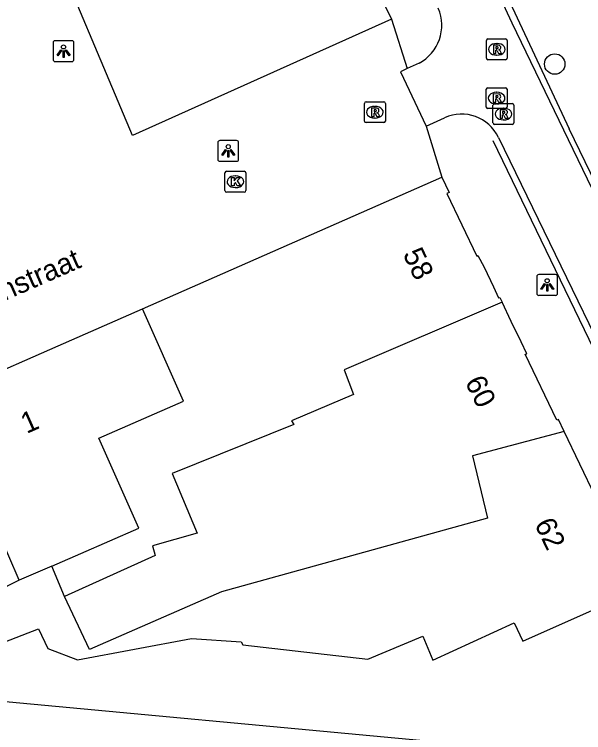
# Model space of a CAD drawing. Extents: x 161087 to 161922, y 382574 to 383873.
# Drawn here: x 161637.33 to 161664.66, y 382920.38 to 382954.87 of the extents above; entities that cross this region are included whole.
import ezdxf

# ---------------------------------------------------------------- set-up
doc = ezdxf.new("R2010")
doc.units = 0
for name, color, linetype in [('IMGEO_Boom', 7, 'Continuous'), ('IMGEO_Kolk', 7, 'Continuous'), ('IMGEO_Lichtpunt', 7, 'Continuous'), ('IMGEO_Lijnafwatering', 7, 'Continuous'), ('IMGEO_Openbare_ruimte_label', 7, 'Continuous'), ('IMGEO_Pand', 7, 'Continuous'), ('IMGEO_Pand_nummerreeks', 7, 'Continuous'), ('IMGEO_Rioolput', 7, 'Continuous'), ('IMGEO_Voetgangersgebied_gesloten', 7, 'Continuous'), ('IMGEO_Voetpad_open', 7, 'Continuous')]:
    doc.layers.add(name, color=color, linetype=linetype)

msp = doc.modelspace()

# ---------------------------------------------------------------- linework, layer by layer
at = {"layer": 'IMGEO_Boom'}
msp.add_circle((161663.274, 382952.485), 0.489, dxfattribs=at)
at = {"layer": 'IMGEO_Kolk'}
for p, q in [((161647.443, 382946.408), (161647.443, 382947.26)), ((161647.518, 382947.334), (161648.37, 382947.334)), ((161648.444, 382947.26), (161648.444, 382946.408)), ((161647.931, 382947.114), (161647.956, 382947.114)), ((161647.954, 382946.554), (161647.929, 382946.554)), ((161648.37, 382946.334), (161647.518, 382946.334))]:
    msp.add_line(p, q, dxfattribs=at)
for points in [[(161647.443, 382946.408), (161647.443, 382947.26)], [(161647.518, 382947.334), (161648.37, 382947.334)], [(161648.444, 382947.26), (161648.444, 382946.408)], [(161647.764, 382947.034), (161647.887, 382947.034), (161647.887, 382946.883), (161648.017, 382947.034), (161648.181, 382947.034), (161648.035, 382946.883), (161648.188, 382946.634), (161648.036, 382946.634), (161647.951, 382946.798), (161647.887, 382946.731), (161647.887, 382946.634), (161647.764, 382946.634), (161647.764, 382947.034)], [(161648.37, 382946.334), (161647.518, 382946.334)]]:
    msp.add_lwpolyline(points, dxfattribs=at)
for centre, start, end in [((161647.52, 382947.258), 91.552, 178.448), ((161647.52, 382947.258), 91.552, 178.448), ((161648.368, 382947.258), 1.552, 88.448), ((161648.368, 382947.258), 1.552, 88.448), ((161647.52, 382946.41), 181.552, 268.448), ((161647.52, 382946.41), 181.552, 268.448), ((161648.368, 382946.41), 271.552, 358.448), ((161648.368, 382946.41), 271.552, 358.448)]:
    msp.add_arc(centre, 0.0765, start, end, dxfattribs=at)
for centre, major_axis, ratio, start_param, end_param in [((161647.93, 382946.834), (-0.387, 0.002), 0.722429, 4.712389, 7.853982), ((161647.955, 382946.834), (-0.39, 0.002), 0.717154, 1.570796, 4.712389)]:
    msp.add_ellipse(centre, major_axis=major_axis, ratio=ratio, start_param=start_param, end_param=end_param, dxfattribs=at)
at = {"layer": 'IMGEO_Lichtpunt'}
for p, q in [((161639.192, 382953.509), (161639.192, 382952.702)), ((161639.192, 382953.509), (161639.192, 382952.702)), ((161640.094, 382953.604), (161639.286, 382953.604)), ((161640.094, 382953.604), (161639.286, 382953.604)), ((161640.188, 382952.702), (161640.188, 382953.509)), ((161640.188, 382952.702), (161640.188, 382953.509)), ((161639.286, 382952.608), (161640.094, 382952.608)), ((161639.286, 382952.608), (161640.094, 382952.608)), ((161647.101, 382948.717), (161647.101, 382947.91)), ((161647.101, 382948.717), (161647.101, 382947.91)), ((161648.003, 382948.812), (161647.195, 382948.812)), ((161648.003, 382948.812), (161647.195, 382948.812)), ((161648.097, 382947.91), (161648.097, 382948.717)), ((161648.097, 382947.91), (161648.097, 382948.717)), ((161647.195, 382947.816), (161648.003, 382947.816)), ((161647.195, 382947.816), (161648.003, 382947.816)), ((161662.414, 382942.279), (161662.414, 382941.472)), ((161662.414, 382942.279), (161662.414, 382941.472)), ((161663.316, 382942.374), (161662.508, 382942.374)), ((161663.316, 382942.374), (161662.508, 382942.374)), ((161663.41, 382941.472), (161663.41, 382942.279)), ((161663.41, 382941.472), (161663.41, 382942.279)), ((161662.508, 382941.378), (161663.316, 382941.378)), ((161662.508, 382941.378), (161663.316, 382941.378))]:
    msp.add_line(p, q, dxfattribs=at)
for points in [[(161639.566, 382953.173), (161639.605, 382953.145), (161639.417, 382952.883), (161639.379, 382952.91), (161639.566, 382953.173)], [(161639.668, 382953.125), (161639.715, 382953.125), (161639.715, 382952.803), (161639.668, 382952.803), (161639.668, 382953.125)], [(161639.778, 382953.145), (161639.816, 382953.172), (161640.003, 382952.91), (161639.964, 382952.882), (161639.778, 382953.145)], [(161647.475, 382948.381), (161647.514, 382948.353), (161647.326, 382948.091), (161647.288, 382948.118), (161647.475, 382948.381)], [(161647.577, 382948.333), (161647.624, 382948.333), (161647.624, 382948.011), (161647.577, 382948.011), (161647.577, 382948.333)], [(161647.687, 382948.353), (161647.725, 382948.38), (161647.912, 382948.118), (161647.873, 382948.09), (161647.687, 382948.353)], [(161662.788, 382941.943), (161662.827, 382941.915), (161662.639, 382941.653), (161662.601, 382941.68), (161662.788, 382941.943)], [(161662.89, 382941.895), (161662.937, 382941.895), (161662.937, 382941.573), (161662.89, 382941.573), (161662.89, 382941.895)], [(161663, 382941.915), (161663.038, 382941.942), (161663.225, 382941.68), (161663.186, 382941.652), (161663, 382941.915)]]:
    msp.add_lwpolyline(points, dxfattribs=at)
for centre in [(161639.691, 382953.307), (161647.6, 382948.515), (161662.913, 382942.077)]:
    msp.add_circle(centre, 0.0994, dxfattribs=at)
for centre, start, end in [((161639.286, 382953.509), 90, 180), ((161639.286, 382953.509), 90, 180), ((161640.094, 382953.509), 0, 90), ((161640.094, 382953.509), 0, 90), ((161639.286, 382952.702), 180, 270), ((161639.286, 382952.702), 180, 270), ((161640.094, 382952.702), 270, 0), ((161640.094, 382952.702), 270, 360), ((161647.195, 382948.717), 90, 180), ((161647.195, 382948.717), 90, 180), ((161648.003, 382948.717), 0, 90), ((161648.003, 382948.717), 0, 90), ((161647.195, 382947.91), 180, 270), ((161647.195, 382947.91), 180, 270), ((161648.003, 382947.91), 270, 0), ((161648.003, 382947.91), 270, 360), ((161662.508, 382942.279), 90, 180), ((161662.508, 382942.279), 90, 180), ((161663.316, 382942.279), 0, 90), ((161663.316, 382942.279), 0, 90), ((161662.508, 382941.472), 180, 270), ((161662.508, 382941.472), 180, 270), ((161663.316, 382941.472), 270, 0), ((161663.316, 382941.472), 270, 360)]:
    msp.add_arc(centre, 0.0946, start, end, dxfattribs=at)
at = {"layer": 'IMGEO_Lijnafwatering'}
for points in [[(161646.729, 382986.194), (161663.964, 382949.371)], [(161675.74, 382925.074), (161663.964, 382949.371)], [(161660.31, 382948.808), (161672.527, 382923.509)]]:
    msp.add_lwpolyline(points, dxfattribs=at)
at = {"layer": 'IMGEO_Pand'}
for points in [[(161655.439, 382954.633), (161643.006, 382949.054), (161638.697, 382959.289), (161626.193, 382950.825), (161625.343, 382952.069)], [(161655.054, 382955.426), (161655.439, 382954.633)], [(161643.484, 382940.731), (161657.862, 382947.045)], [(161657.862, 382947.045), (161658.208, 382946.323), (161658.091, 382946.266), (161659.532, 382943.261), (161659.589, 382943.296), (161659.885, 382942.731), (161660.336, 382941.783), (161660.577, 382941.261), (161660.636, 382941.271), (161660.745, 382941.043)], [(161660.745, 382941.043), (161653.163, 382937.804), (161653.617, 382936.609), (161650.638, 382935.344), (161650.748, 382935.18), (161644.908, 382932.825), (161646.11, 382929.955), (161643.965, 382929.344), (161644.094, 382928.879), (161639.738, 382926.918)], [(161663.732, 382934.836), (161663.457, 382935.408), (161663.379, 382935.386), (161661.86, 382938.545), (161661.938, 382938.563), (161661.662, 382939.138), (161661.183, 382940.128), (161660.745, 382941.043)], [(161634.051, 382936.588), (161635.28, 382937.128), (161639.428, 382938.95), (161643.484, 382940.731)], [(161639.126, 382928.376), (161643.302, 382930.204), (161641.393, 382934.514), (161645.452, 382936.291), (161643.484, 382940.731)], [(161663.732, 382934.836), (161659.32, 382933.67), (161660.052, 382930.681), (161647.274, 382927.136), (161640.934, 382924.374), (161639.738, 382926.918)], [(161667.399, 382927.281), (161665.99, 382930.134), (161663.732, 382934.836)], [(161637.568, 382927.694), (161636.555, 382930.011)], [(161639.126, 382928.376), (161637.568, 382927.694)], [(161639.738, 382926.918), (161639.126, 382928.376)], [(161637.568, 382927.694), (161636.378, 382927.106)], [(161636.378, 382927.106), (161636.612, 382924.641), (161638.495, 382925.369), (161638.941, 382924.412), (161640.368, 382923.88), (161645.84, 382924.901), (161648.221, 382924.746), (161648.306, 382924.594), (161654.296, 382923.905), (161656.944, 382925.011), (161657.424, 382923.853), (161661.322, 382925.645), (161661.745, 382924.763), (161667.399, 382927.281)], [(161664.212, 382919.123), (161658.688, 382919.827), (161633.982, 382922.123), (161627.845, 382919.44), (161626.374, 382922.805)]]:
    msp.add_lwpolyline(points, dxfattribs=at)
at = {"layer": 'IMGEO_Rioolput'}
for p, q in [((161659.991, 382952.765), (161659.991, 382953.617)), ((161660.066, 382953.691), (161660.918, 382953.691)), ((161660.479, 382953.471), (161660.504, 382953.471)), ((161660.992, 382953.617), (161660.992, 382952.765)), ((161660.502, 382952.911), (161660.477, 382952.911)), ((161660.918, 382952.691), (161660.066, 382952.691)), ((161660.06, 382951.347), (161660.912, 382951.347)), ((161659.985, 382950.421), (161659.985, 382951.273)), ((161660.473, 382951.127), (161660.498, 382951.127)), ((161660.986, 382951.273), (161660.986, 382950.421)), ((161654.216, 382950.671), (161655.068, 382950.671)), ((161654.141, 382949.745), (161654.141, 382950.597)), ((161654.629, 382950.451), (161654.654, 382950.451)), ((161655.142, 382950.597), (161655.142, 382949.745)), ((161660.912, 382950.347), (161660.06, 382950.347)), ((161660.311, 382949.658), (161660.311, 382950.51)), ((161660.386, 382950.584), (161661.238, 382950.584)), ((161660.496, 382950.567), (161660.471, 382950.567)), ((161660.799, 382950.364), (161660.824, 382950.364)), ((161661.312, 382950.51), (161661.312, 382949.658)), ((161655.068, 382949.671), (161654.216, 382949.671)), ((161654.652, 382949.891), (161654.627, 382949.891)), ((161660.822, 382949.804), (161660.797, 382949.804)), ((161661.238, 382949.584), (161660.386, 382949.584))]:
    msp.add_line(p, q, dxfattribs=at)
for points in [[(161659.991, 382952.765), (161659.991, 382953.617)], [(161660.066, 382953.691), (161660.918, 382953.691)], [(161660.992, 382953.617), (161660.992, 382952.765)], [(161660.58, 382953.389), (161660.328, 382953.391), (161660.328, 382952.991)], [(161660.328, 382952.991), (161660.452, 382952.991), (161660.452, 382953.153), (161660.463, 382953.153)], [(161660.506, 382953.31), (161660.452, 382953.31), (161660.452, 382953.229)], [(161660.452, 382953.229), (161660.504, 382953.229)], [(161660.51, 382953.124), (161660.581, 382952.991), (161660.721, 382952.991), (161660.656, 382953.117)], [(161660.918, 382952.691), (161660.066, 382952.691)], [(161660.06, 382951.347), (161660.912, 382951.347)], [(161659.985, 382950.421), (161659.985, 382951.273)], [(161660.574, 382951.045), (161660.322, 382951.047), (161660.322, 382950.647)], [(161660.986, 382951.273), (161660.986, 382950.421)], [(161654.216, 382950.671), (161655.068, 382950.671)], [(161660.322, 382950.647), (161660.446, 382950.647), (161660.446, 382950.809), (161660.457, 382950.809)], [(161660.5, 382950.966), (161660.446, 382950.966), (161660.446, 382950.885)], [(161660.446, 382950.885), (161660.498, 382950.885)], [(161660.504, 382950.78), (161660.575, 382950.647), (161660.715, 382950.647), (161660.65, 382950.773)], [(161654.141, 382949.745), (161654.141, 382950.597)], [(161654.73, 382950.369), (161654.478, 382950.371), (161654.478, 382949.971)], [(161655.142, 382950.597), (161655.142, 382949.745)], [(161660.912, 382950.347), (161660.06, 382950.347)], [(161660.311, 382949.658), (161660.311, 382950.51)], [(161660.386, 382950.584), (161661.238, 382950.584)], [(161661.312, 382950.51), (161661.312, 382949.658)], [(161654.478, 382949.971), (161654.602, 382949.971), (161654.602, 382950.133), (161654.613, 382950.133)], [(161654.656, 382950.29), (161654.602, 382950.29), (161654.602, 382950.209)], [(161654.602, 382950.209), (161654.654, 382950.209)], [(161654.66, 382950.104), (161654.731, 382949.971), (161654.871, 382949.971), (161654.806, 382950.097)], [(161660.9, 382950.282), (161660.648, 382950.284), (161660.648, 382949.884)], [(161660.648, 382949.884), (161660.772, 382949.884), (161660.772, 382950.046), (161660.783, 382950.046)], [(161660.826, 382950.203), (161660.772, 382950.203), (161660.772, 382950.122)], [(161660.772, 382950.122), (161660.824, 382950.122)], [(161660.83, 382950.017), (161660.901, 382949.884), (161661.041, 382949.884), (161660.976, 382950.01)], [(161655.068, 382949.671), (161654.216, 382949.671)], [(161661.238, 382949.584), (161660.386, 382949.584)]]:
    msp.add_lwpolyline(points, dxfattribs=at)
for centre, radius, start, end in [((161660.068, 382953.615), 0.0765, 91.552, 178.448), ((161660.068, 382953.615), 0.0765, 91.552, 178.448), ((161660.916, 382953.615), 0.0765, 1.552, 88.448), ((161660.916, 382953.615), 0.0765, 1.552, 88.448), ((161660.462, 382953.1), 0.0533, 26.0293, 88.6989), ((161660.488, 382953.418), 0.19, 274.7715, 282.9687), ((161660.512, 382953.214), 0.0964, 77.0061, 93.1865), ((161660.526, 382953.271), 0.0378, 276.6634, 79.6772), ((161660.579, 382953.279), 0.109, 350.3612, 89.416), ((161660.577, 382953.279), 0.112, 277.5842, 350.9817), ((161660.561, 382953.064), 0.108, 29.5134, 73.7905), ((161660.068, 382952.767), 0.0765, 181.552, 268.448), ((161660.068, 382952.767), 0.0765, 181.552, 268.448), ((161660.916, 382952.767), 0.0765, 271.552, 358.448), ((161660.916, 382952.767), 0.0765, 271.552, 358.448), ((161660.062, 382951.271), 0.0765, 91.552, 178.448), ((161660.062, 382951.271), 0.0765, 91.552, 178.448), ((161660.91, 382951.271), 0.0765, 1.552, 88.448), ((161660.91, 382951.271), 0.0765, 1.552, 88.448), ((161660.573, 382950.935), 0.109, 350.3612, 89.416), ((161654.218, 382950.595), 0.0765, 91.552, 178.448), ((161654.218, 382950.595), 0.0765, 91.552, 178.448), ((161655.066, 382950.595), 0.0765, 1.552, 88.448), ((161655.066, 382950.595), 0.0765, 1.552, 88.448), ((161660.456, 382950.756), 0.0533, 26.0293, 88.6989), ((161660.482, 382951.074), 0.19, 274.7715, 282.9687), ((161660.506, 382950.87), 0.0964, 77.0061, 93.1865), ((161660.52, 382950.927), 0.0378, 276.6634, 79.6772), ((161660.571, 382950.935), 0.112, 277.5842, 350.9817), ((161660.555, 382950.72), 0.108, 29.5134, 73.7905), ((161654.729, 382950.259), 0.109, 350.3612, 89.416), ((161660.062, 382950.423), 0.0765, 181.552, 268.448), ((161660.062, 382950.423), 0.0765, 181.552, 268.448), ((161660.388, 382950.508), 0.0765, 91.552, 178.448), ((161660.388, 382950.508), 0.0765, 91.552, 178.448), ((161660.91, 382950.423), 0.0765, 271.552, 358.448), ((161660.91, 382950.423), 0.0765, 271.552, 358.448), ((161661.236, 382950.508), 0.0765, 1.552, 88.448), ((161661.236, 382950.508), 0.0765, 1.552, 88.448), ((161654.612, 382950.08), 0.0533, 26.0293, 88.6989), ((161654.638, 382950.398), 0.19, 274.7715, 282.9687), ((161654.662, 382950.194), 0.0964, 77.0061, 93.1865), ((161654.676, 382950.251), 0.0378, 276.6634, 79.6772), ((161654.727, 382950.259), 0.112, 277.5842, 350.9817), ((161654.711, 382950.044), 0.108, 29.5134, 73.7905), ((161660.782, 382949.993), 0.0533, 26.0293, 88.6989), ((161660.808, 382950.311), 0.19, 274.7715, 282.9687), ((161660.832, 382950.107), 0.0964, 77.0061, 93.1865), ((161660.846, 382950.164), 0.0378, 276.6634, 79.6772), ((161660.899, 382950.172), 0.109, 350.3612, 89.416), ((161660.897, 382950.172), 0.112, 277.5842, 350.9817), ((161660.881, 382949.957), 0.108, 29.5134, 73.7905), ((161654.218, 382949.747), 0.0765, 181.552, 268.448), ((161654.218, 382949.747), 0.0765, 181.552, 268.448), ((161655.066, 382949.747), 0.0765, 271.552, 358.448), ((161655.066, 382949.747), 0.0765, 271.552, 358.448), ((161660.388, 382949.66), 0.0765, 181.552, 268.448), ((161660.388, 382949.66), 0.0765, 181.552, 268.448), ((161661.236, 382949.66), 0.0765, 271.552, 358.448), ((161661.236, 382949.66), 0.0765, 271.552, 358.448)]:
    msp.add_arc(centre, radius, start, end, dxfattribs=at)
for centre, major_axis, ratio, start_param, end_param in [((161660.478, 382953.191), (-0.387, 0.002), 0.722429, 4.712389, 7.853982), ((161660.503, 382953.191), (-0.39, 0.002), 0.717154, 1.570796, 4.712389), ((161660.472, 382950.847), (-0.387, 0.002), 0.722429, 4.712389, 7.853982), ((161660.497, 382950.847), (-0.39, 0.002), 0.717154, 1.570796, 4.712389), ((161654.628, 382950.171), (-0.387, 0.002), 0.722429, 4.712389, 7.853982), ((161654.653, 382950.171), (-0.39, 0.002), 0.717154, 1.570796, 4.712389), ((161660.798, 382950.084), (-0.387, 0.002), 0.722429, 4.712389, 7.853982), ((161660.823, 382950.084), (-0.39, 0.002), 0.717154, 1.570796, 4.712389)]:
    msp.add_ellipse(centre, major_axis=major_axis, ratio=ratio, start_param=start_param, end_param=end_param, dxfattribs=at)
at = {"layer": 'IMGEO_Voetgangersgebied_gesloten'}
for points in [[(161679.531, 382916.561), (161661.239, 382954.441), (161646.183, 382986.769)], [(161656.762, 382952.524), (161656.195, 382952.265)], [(161657.109, 382949.507), (161657.99, 382949.906)], [(161660.568, 382948.962), (161676.869, 382915.408)]]:
    msp.add_lwpolyline(points, dxfattribs=at)
for centre, radius, start, end in [((161655.788, 382954.346), 2.066, 298.1292, 23.3429), ((161658.801, 382948.13), 1.953, 25.2307, 114.5464)]:
    msp.add_arc(centre, radius, start, end, dxfattribs=at)
at = {"layer": 'IMGEO_Voetpad_open'}
for points in [[(161655.439, 382954.633), (161656.195, 382952.265)], [(161656.195, 382952.265), (161655.873, 382952.118), (161657.109, 382949.507)], [(161657.109, 382949.507), (161657.862, 382947.045)]]:
    msp.add_lwpolyline(points, dxfattribs=at)

# ---------------------------------------------------------------- texts
at = {"layer": 'IMGEO_Openbare_ruimte_label'}
msp.add_text('Molenstraat', height=1, rotation=23.6425, dxfattribs=at).set_placement((161634.207, 382939.943))
at = {"layer": 'IMGEO_Pand_nummerreeks'}
for s, rotation, p in [('58', 295.4678, (161655.964, 382943.365)), ('60', 296.4361, (161658.943, 382937.217)), ('1', 23.9611, (161637.918, 382934.718)), ('62', 295.6339, (161662.285, 382930.398))]:
    msp.add_text(s, height=1, rotation=rotation, dxfattribs=at).set_placement(p)

doc.saveas('drawing.dxf')
